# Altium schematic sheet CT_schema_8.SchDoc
size 403 x 220 mm
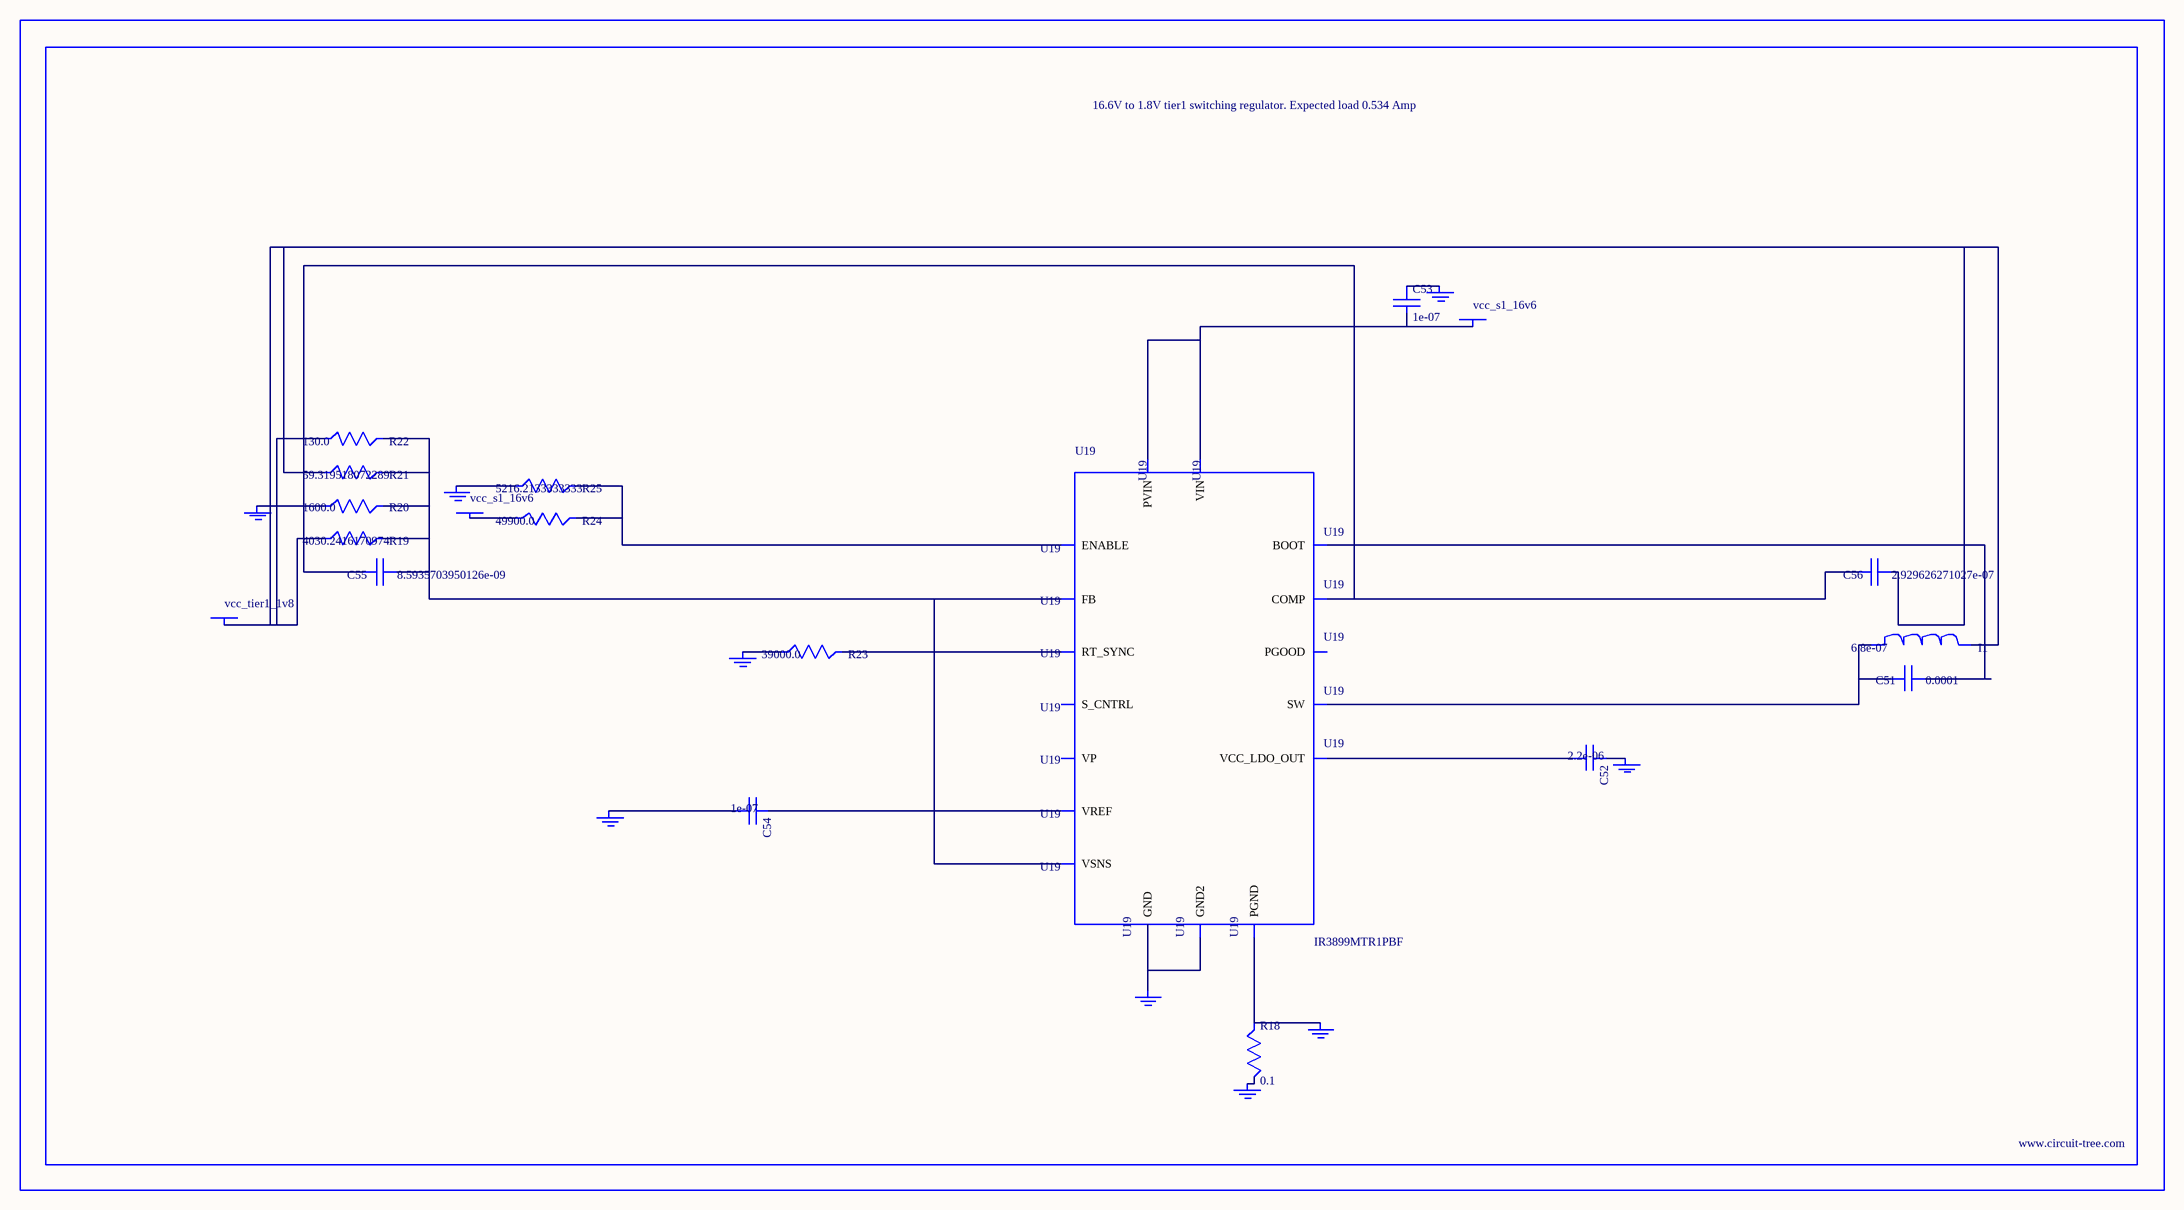
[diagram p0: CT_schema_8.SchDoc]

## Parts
BORDER7  (no value)
C51  0.0001  [C1210]
C52  2.2e-06  [C0603]
C53  1e-07  [C0402]
C54  1e-07  [C0402]
C55  8.5935703950126e-09  [R0603]
C56  2.929626271027e-07  [R0603]
GND_INSTANCE_7_0  (no value)
GND_INSTANCE_7_1  (no value)
GND_INSTANCE_7_2  (no value)
GND_INSTANCE_7_3  (no value)
GND_INSTANCE_7_4  (no value)
GND_INSTANCE_7_5  (no value)
GND_INSTANCE_7_6  (no value)
GND_INSTANCE_7_7  (no value)
GND_INSTANCE_7_8  (no value)
I1  6.8e-07  [IND25X25CZ]
POWER_INSTANCE_7_0  vcc_s1_16v6
POWER_INSTANCE_7_1  vcc_s1_16v6
POWER_INSTANCE_7_2  vcc_tier1_1v8
R18  0.1  [R0603]
R19  4030.2416170974  [R0603]
R20  1600.0  [R0603]
R21  59.319518072289  [R0603]
R22  130.0  [R0603]
R23  39000.0  [R0603]
R24  49900.0  [R0603]
R25  5216.2133333333  [R0603]
U19  IR3899MTR1PBF  [IR3899MTR1PBF]

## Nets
NetC51_1: C51.1 U19.14(BOOT)
NetC51_2: C51.2 I1.1 U19.12(SW)
NetC52_1: C52.1 GND_INSTANCE_7_4.0(GND)
NetC52_2: C52.2 U19.10(VCC_LDO_OUT)
NetC53_1: C53.1 GND_INSTANCE_7_3.0(GND)
NetC53_2: C53.2 POWER_INSTANCE_7_0.0(PWR) U19.9(VIN) U19.13(PVIN)
NetC54_1: C54.1 U19.2(VREF)
NetC54_2: C54.2 GND_INSTANCE_7_1.0(GND)
NetC55_1: C55.1 R19.2 R20.2 R21.2 R22.2 U19.1(FB) U19.8(VSNS)
NetC55_2: C55.2 C56.2 U19.3(COMP)
NetC56_1: C56.1 I1.2 POWER_INSTANCE_7_2.0(PWR) R19.1 R21.1 R22.1
NetGND_INSTANCE_7_0_0: GND_INSTANCE_7_0.0(GND) R20.1
NetGND_INSTANCE_7_2_0: GND_INSTANCE_7_2.0(GND) R23.1
NetGND_INSTANCE_7_5_0: GND_INSTANCE_7_5.0(GND) R18.2
NetGND_INSTANCE_7_6_0: GND_INSTANCE_7_6.0(GND) R18.1 U19.11(PGND)
NetGND_INSTANCE_7_7_0: GND_INSTANCE_7_7.0(GND) R25.1
NetGND_INSTANCE_7_8_0: GND_INSTANCE_7_8.0(GND) U19.4(GND) U19.17(GND2)
NetPOWER_INSTANCE_7_1_0: POWER_INSTANCE_7_1.0(PWR) R24.1
NetR23_2: R23.2 U19.5(RT_SYNC)
NetR24_2: R24.2 R25.2 U19.15(ENABLE)

Not connected (* = marked no-connect by the designer): U19 6(S_CNTRL) 7(PGOOD) 16(VP)

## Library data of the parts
BORDER7 = BORDER_PAGE7
C51 = GRM32ER61A107ME20L
C52 = C0603C225K8RACTU
C53 C54 = C0402C104K3RACTU
C55 = C55
C56 = C56
GND_INSTANCE_7_0-GND_INSTANCE_7_8 = GND
I1 = IHLP2525CZERR68M01
POWER_INSTANCE_7_0-POWER_INSTANCE_7_2 = PWR
R18 = ERJ-3RSFR10V
R19 = R19
R20 = RC0603JR-071K6L
R21 = R21
R22 = RC0603JR-07130RL
R23 = RC0603JR-0739KL
R24 = RC0603FR-0749K9
R25 = R25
